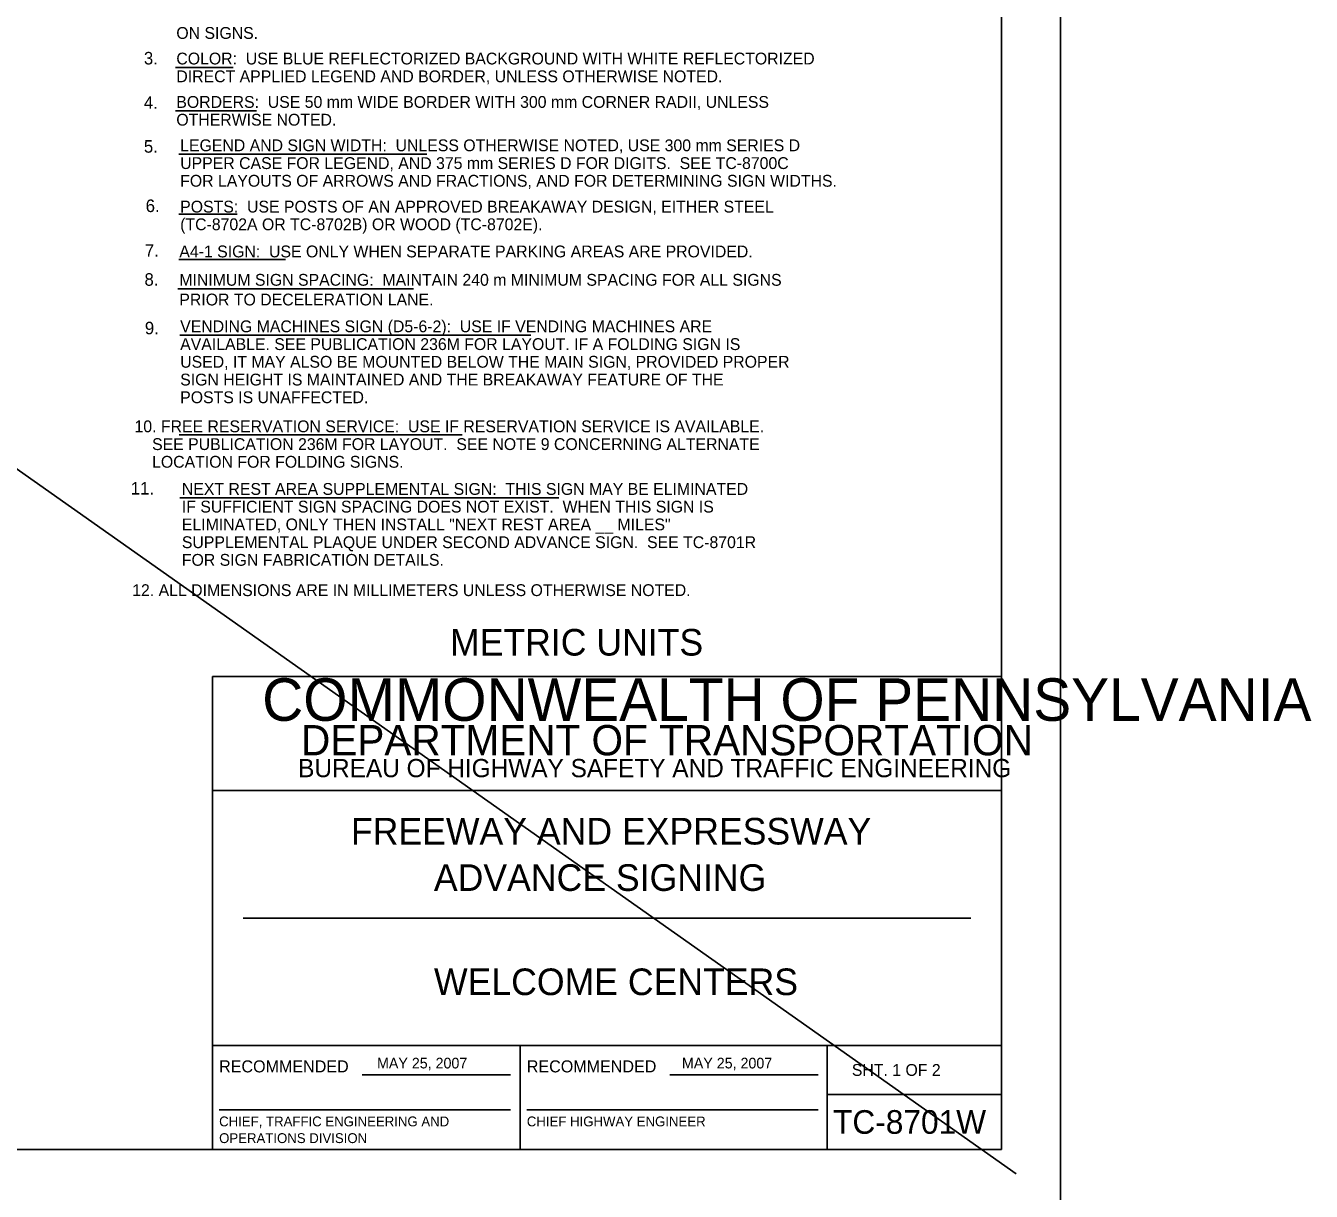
# Model space of a CAD drawing. Extents: x 2189973 to 2192941, y 2147557 to 2151454.
# Drawn here: x 2191872 to 2192941, y 2149520 to 2150490 of the extents above; entities that cross this region are included whole.
import ezdxf

# ---------------------------------------------------------------- set-up
doc = ezdxf.new("R2010")
doc.units = 0
for name, color, linetype in [('1', 7, 'Continuous'), ('Default', 7, 'Continuous'), ('PLT-BNDY', 7, 'Continuous')]:
    doc.layers.add(name, color=color, linetype=linetype)

msp = doc.modelspace()

# ---------------------------------------------------------------- linework, layer by layer
at = {"layer": '1'}
msp.add_line((2190017.3, 2151423.8), (2192695.6, 2149534.5), dxfattribs=at)
at = {"layer": 'Default'}
for p, q in [((2192683.2, 2149554.8), (2192683.2, 2151405.2)), ((2191996.2, 2150455.2), (2192044.2, 2150455.2)), ((2191996.2, 2150419.1), (2192063.6, 2150419.1)), ((2191999, 2150382.9), (2192205.3, 2150382.9)), ((2191999, 2150333.1), (2192047.7, 2150333.1)), ((2191999, 2150295.4), (2192087.9, 2150295.4)), ((2191998.2, 2150271), (2192194.3, 2150271)), ((2191999.8, 2150232.3), (2192291.7, 2150232.3)), ((2191999.3, 2150149.4), (2192234.8, 2150149.4)), ((2191999.8, 2150097), (2192315, 2150097)), ((2192027, 2149554.8), (2192027, 2149948.5)), ((2192027, 2149948.5), (2192683.2, 2149948.5)), ((2192683.2, 2149853.4), (2192027, 2149853.4)), ((2192052.5, 2149747.4), (2192657.8, 2149747.4)), ((2192027, 2149641.3), (2192683.2, 2149641.3)), ((2192283, 2149641.3), (2192283, 2149554.8)), ((2192538.4, 2149554.8), (2192538.4, 2149641.3)), ((2192151.5, 2149617), (2192274.9, 2149617)), ((2192407.4, 2149617), (2192530.8, 2149617)), ((2192538.4, 2149600.7), (2192683.2, 2149600.7)), ((2192032.6, 2149587.8), (2192274.9, 2149587.8)), ((2192288.5, 2149587.8), (2192530.8, 2149587.8)), ((2192683.2, 2149554.8), (2190104.5, 2149554.8)), ((2190104.5, 2149554.8), (2192027, 2149554.8))]:
    msp.add_line(p, q, dxfattribs=at)
at = {"layer": 'PLT-BNDY'}
msp.add_lwpolyline([(2189973.2, 2151454.4), (2192732.4, 2151454.4), (2192732.4, 2149505.6), (2189973.2, 2149505.6)], close=True, dxfattribs=at)

# ---------------------------------------------------------------- texts
at = {"layer": 'Default'}
for s, height, p in [('ON SIGNS.', 9.84, (2191997, 2150478.9)), ('COLOR:  USE BLUE REFLECTORIZED BACKGROUND WITH WHITE REFLECTORIZED', 9.842, (2191997, 2150457.6)), ('DIRECT APPLIED LEGEND AND BORDER, UNLESS OTHERWISE NOTED.', 9.842, (2191997, 2150442.8)), ('BORDERS:  USE 50 mm WIDE BORDER WITH 300 mm CORNER RADII, UNLESS', 9.842, (2191997, 2150421.5)), ('OTHERWISE NOTED.', 9.842, (2191997, 2150406.7)), ('LEGEND AND SIGN WIDTH:  UNLESS OTHERWISE NOTED, USE 300 mm SERIES D', 9.842, (2192000.2, 2150385.4)), ('UPPER CASE FOR LEGEND, AND 375 mm SERIES D FOR DIGITS.  SEE TC-8700C', 9.842, (2192000.2, 2150370.6)), ('FOR LAYOUTS OF ARROWS AND FRACTIONS, AND FOR DETERMINING SIGN WIDTHS.', 9.842, (2192000.2, 2150355.9)), ('POSTS:  USE POSTS OF AN APPROVED BREAKAWAY DESIGN, EITHER STEEL', 9.842, (2192000.2, 2150334.4)), ('(TC-8702A OR TC-8702B) OR WOOD (TC-8702E).', 9.842, (2192000.2, 2150319.7)), ('A4-1 SIGN:  USE ONLY WHEN SEPARATE PARKING AREAS ARE PROVIDED.', 9.842, (2191999.5, 2150297.1)), ('MINIMUM SIGN SPACING:  MAINTAIN 240 m MINIMUM SPACING FOR ALL SIGNS', 9.842, (2191999.5, 2150273.5)), ('PRIOR TO DECELERATION LANE.', 9.842, (2191999.5, 2150257.1)), ('VENDING MACHINES SIGN (D5-6-2):  USE IF VENDING MACHINES ARE', 9.842, (2192000.2, 2150234.8)), ('AVAILABLE. SEE PUBLICATION 236M FOR LAYOUT. IF A FOLDING SIGN IS', 9.842, (2192000.2, 2150220)), ('USED, IT MAY ALSO BE MOUNTED BELOW THE MAIN SIGN, PROVIDED PROPER', 9.842, (2192000.2, 2150205.3)), ('SIGN HEIGHT IS MAINTAINED AND THE BREAKAWAY FEATURE OF THE', 9.842, (2192000.2, 2150190.5)), ('POSTS IS UNAFFECTED.', 9.842, (2192000.2, 2150175.8)), ('10. FREE RESERVATION SERVICE:  USE IF RESERVATION SERVICE IS AVAILABLE.', 9.842, (2191962.2, 2150151.6)), ('    SEE PUBLICATION 236M FOR LAYOUT.  SEE NOTE 9 CONCERNING ALTERNATE', 9.842, (2191962.2, 2150136.8)), ('    LOCATION FOR FOLDING SIGNS.', 9.842, (2191962.2, 2150122.1)), ('11.', 10.44, (2191959.1, 2150099.8)), ('NEXT REST AREA SUPPLEMENTAL SIGN:  THIS SIGN MAY BE ELIMINATED', 9.842, (2192001.6, 2150099.5)), ('IF SUFFICIENT SIGN SPACING DOES NOT EXIST.  WHEN THIS SIGN IS', 9.842, (2192001.6, 2150084.8)), ('ELIMINATED, ONLY THEN INSTALL "NEXT REST AREA __ MILES" ', 9.842, (2192001.6, 2150070)), ('SUPPLEMENTAL PLAQUE UNDER SECOND ADVANCE SIGN.  SEE TC-8701R', 9.842, (2192001.6, 2150055.2)), ('FOR SIGN FABRICATION DETAILS.', 9.842, (2192001.6, 2150040.5)), ('12. ALL DIMENSIONS ARE IN MILLIMETERS UNLESS OTHERWISE NOTED.', 9.842, (2191960.3, 2150015.3)), ('METRIC UNITS', 22.146, (2192224.6, 2149965.8)), ('COMMONWEALTH OF PENNSYLVANIA', 35.376, (2192068.4, 2149911.5)), ('DEPARTMENT OF TRANSPORTATION', 25.209, (2192100.7, 2149882.8)), ('BUREAU OF HIGHWAY SAFETY AND TRAFFIC ENGINEERING', 15.175, (2192098.3, 2149864.6)), ('FREEWAY AND EXPRESSWAY', 22.146, (2192142.2, 2149808.6)), ('ADVANCE SIGNING', 22.146, (2192211.2, 2149770)), ('WELCOME CENTERS', 22.146, (2192211.3, 2149683.3)), ('RECOMMENDED', 10, (2192032.6, 2149619)), ('MAY 25, 2007', 8.858, (2192163.9, 2149622.3)), ('RECOMMENDED', 10, (2192288.5, 2149619)), ('MAY 25, 2007', 8.858, (2192417.5, 2149622.3)), ('SHT. 1 OF 2', 9.842, (2192558.8, 2149616.1)), ('TC-8701W', 19.68, (2192543.2, 2149567.9)), ('CHIEF, TRAFFIC ENGINEERING AND', 8.202, (2192032.6, 2149574.1)), ('CHIEF HIGHWAY ENGINEER', 8.202, (2192288.5, 2149574.1)), ('OPERATIONS DIVISION', 8.202, (2192032.6, 2149560.2))]:
    msp.add_text(s, height=height, dxfattribs=at).set_placement(p)
for s, p in [('3.  ', (2191970, 2150457.6)), ('4.  ', (2191970, 2150420.7)), ('5.  ', (2191970, 2150384.2)), ('6.  ', (2191971.5, 2150334.8)), ('7.  ', (2191970.8, 2150297.6)), ('8.  ', (2191970.5, 2150273.5)), ('9.', (2191970.8, 2150233.1))]:
    msp.add_text(s, height=10.44, rotation=360, dxfattribs=at).set_placement(p)

doc.saveas('drawing.dxf')
